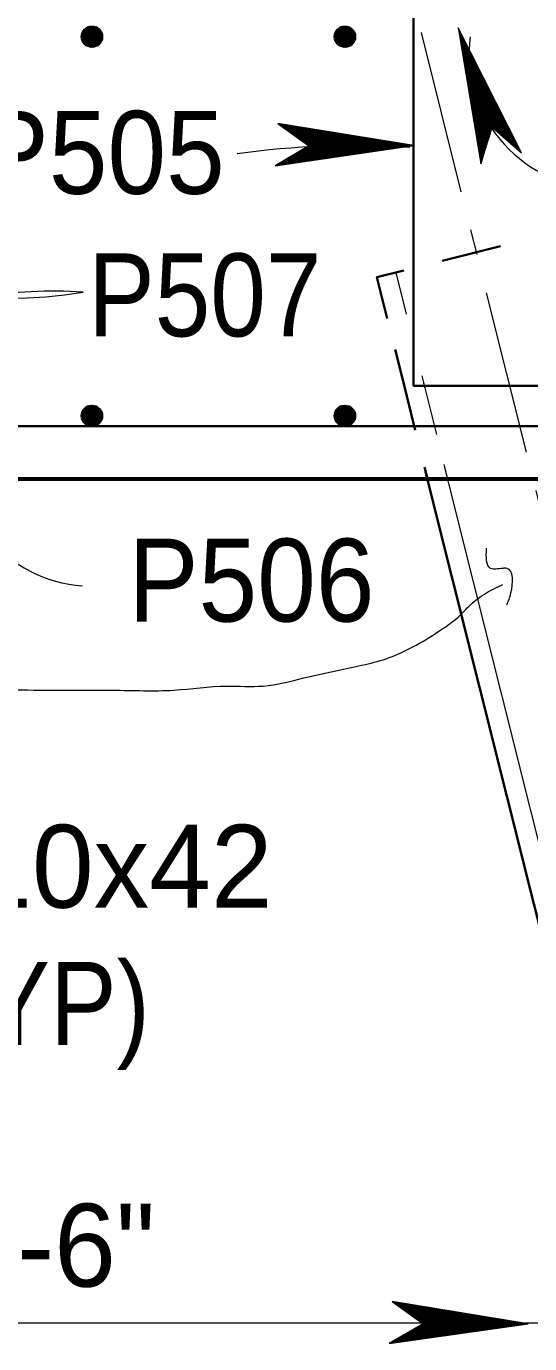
# Model space of a CAD drawing. Extents: x 144 to 252, y 360 to 425.
# Drawn here: x 193.57 to 195.56, y 408.41 to 413.62 of the extents above; entities that cross this region are included whole.
import ezdxf
from ezdxf.enums import TextEntityAlignment as Align

# ---------------------------------------------------------------- set-up
doc = ezdxf.new("R2010")
doc.units = 0
doc.header["$LTSCALE"] = 0.13
doc.linetypes.add('DOT_DASHED', pattern=[7.7, 5, -1.2, 0.3, -1.2])
for name, color, linetype, lineweight in [('1', 7, 'Continuous', 40), ('14', 7, 'Continuous', 13), ('16', 7, 'Continuous', 13), ('3', 7, 'Continuous', 13), ('4', 7, 'Continuous', 35), ('5', 7, 'Continuous', 35)]:
    doc.layers.add(name, color=color, linetype=linetype, lineweight=lineweight)

msp = doc.modelspace()

# ---------------------------------------------------------------- linework, layer by layer
at = {"layer": '1'}
for p, q in [((193.799, 413.6072), (193.7965, 413.5623)), ((193.8015, 413.6072), (193.799, 413.5623)), ((193.799, 413.6072), (193.859, 413.5972)), ((193.799, 413.6047), (193.859, 413.5947)), ((193.799, 413.6022), (193.859, 413.5897)), ((193.799, 413.5997), (193.859, 413.5872)), ((193.799, 413.5947), (193.8565, 413.5847)), ((193.8015, 413.6122), (193.859, 413.6022)), ((193.804, 413.6072), (193.8015, 413.5623)), ((193.8065, 413.6072), (193.804, 413.5623)), ((193.809, 413.6072), (193.8065, 413.5623)), ((193.814, 413.6072), (193.8115, 413.5623)), ((193.8165, 413.6072), (193.814, 413.5623)), ((193.819, 413.6072), (193.8165, 413.5623)), ((193.8215, 413.6072), (193.819, 413.5623)), ((193.824, 413.6072), (193.8215, 413.5623)), ((193.8265, 413.6072), (193.824, 413.5623)), ((193.829, 413.6072), (193.8265, 413.5623)), ((193.834, 413.6047), (193.829, 413.5598)), ((193.839, 413.6047), (193.834, 413.5598)), ((193.8415, 413.6047), (193.839, 413.5598)), ((193.8415, 413.6047), (193.839, 413.5598)), ((193.844, 413.6047), (193.8415, 413.5598)), ((193.8465, 413.6047), (193.844, 413.5598)), ((193.849, 413.6047), (193.8465, 413.5598)), ((193.8515, 413.6047), (193.849, 413.5598)), ((193.854, 413.6047), (193.8515, 413.5598)), ((193.8565, 413.6047), (193.854, 413.5598)), ((193.8615, 413.6047), (193.859, 413.5598)), ((194.799, 413.6072), (194.7965, 413.5623)), ((194.8015, 413.6072), (194.799, 413.5623)), ((194.799, 413.6072), (194.859, 413.5972)), ((194.799, 413.6047), (194.859, 413.5947)), ((194.799, 413.6022), (194.859, 413.5897)), ((194.799, 413.5997), (194.859, 413.5872)), ((194.799, 413.5947), (194.8565, 413.5847)), ((194.8015, 413.6122), (194.859, 413.6022)), ((194.804, 413.6072), (194.8015, 413.5623)), ((194.8065, 413.6072), (194.804, 413.5623)), ((194.809, 413.6072), (194.8065, 413.5623)), ((194.814, 413.6072), (194.8115, 413.5623)), ((194.8165, 413.6072), (194.814, 413.5623)), ((194.819, 413.6072), (194.8165, 413.5623)), ((194.8215, 413.6072), (194.819, 413.5623)), ((194.824, 413.6072), (194.8215, 413.5623)), ((194.8265, 413.6072), (194.824, 413.5623)), ((194.829, 413.6072), (194.8265, 413.5623)), ((194.834, 413.6047), (194.829, 413.5598)), ((194.839, 413.6047), (194.834, 413.5598)), ((194.8415, 413.6047), (194.839, 413.5598)), ((194.8415, 413.6047), (194.839, 413.5598)), ((194.844, 413.6047), (194.8415, 413.5598)), ((194.8465, 413.6047), (194.844, 413.5598)), ((194.849, 413.6047), (194.8465, 413.5598)), ((194.8515, 413.6047), (194.849, 413.5598)), ((194.854, 413.6047), (194.8515, 413.5598)), ((194.8565, 413.6047), (194.854, 413.5598)), ((194.8615, 413.6047), (194.859, 413.5598)), ((193.7915, 413.5648), (193.8515, 413.5548)), ((193.794, 413.5797), (193.854, 413.5673)), ((193.794, 413.5722), (193.854, 413.5623)), ((193.794, 413.5697), (193.8515, 413.5598)), ((193.794, 413.5673), (193.8515, 413.5573)), ((193.7965, 413.5922), (193.8565, 413.5822)), ((193.7965, 413.5897), (193.8565, 413.5772)), ((193.7965, 413.5872), (193.854, 413.5747)), ((193.7965, 413.5847), (193.854, 413.5722)), ((194.7915, 413.5648), (194.8515, 413.5548)), ((194.794, 413.5797), (194.854, 413.5673)), ((194.794, 413.5722), (194.854, 413.5623)), ((194.794, 413.5697), (194.8515, 413.5598)), ((194.794, 413.5673), (194.8515, 413.5573)), ((194.7965, 413.5922), (194.8565, 413.5822)), ((194.7965, 413.5897), (194.8565, 413.5772)), ((194.7965, 413.5872), (194.854, 413.5747)), ((194.7965, 413.5847), (194.854, 413.5722)), ((193.799, 412.1072), (193.7965, 412.0623)), ((193.7965, 412.0922), (193.8565, 412.0822)), ((193.7965, 412.0897), (193.8565, 412.0772)), ((193.7965, 412.0872), (193.854, 412.0747)), ((193.7965, 412.0847), (193.854, 412.0722)), ((193.8015, 412.1072), (193.799, 412.0623)), ((193.799, 412.1072), (193.859, 412.0972)), ((193.799, 412.1047), (193.859, 412.0947)), ((193.799, 412.1022), (193.859, 412.0897)), ((193.799, 412.0997), (193.859, 412.0872)), ((193.799, 412.0947), (193.8565, 412.0847)), ((193.8015, 412.1122), (193.859, 412.1022)), ((193.804, 412.1072), (193.8015, 412.0623)), ((193.8065, 412.1072), (193.804, 412.0623)), ((193.809, 412.1072), (193.8065, 412.0623)), ((193.814, 412.1072), (193.8115, 412.0623)), ((193.8165, 412.1072), (193.814, 412.0623)), ((193.819, 412.1072), (193.8165, 412.0623)), ((193.8215, 412.1072), (193.819, 412.0623)), ((193.824, 412.1072), (193.8215, 412.0623)), ((193.8265, 412.1072), (193.824, 412.0623)), ((193.829, 412.1072), (193.8265, 412.0623)), ((193.834, 412.1047), (193.829, 412.0598)), ((193.839, 412.1047), (193.834, 412.0598)), ((193.8415, 412.1047), (193.839, 412.0598)), ((193.8415, 412.1047), (193.839, 412.0598)), ((193.844, 412.1047), (193.8415, 412.0598)), ((193.8465, 412.1047), (193.844, 412.0598)), ((193.849, 412.1047), (193.8465, 412.0598)), ((193.8515, 412.1047), (193.849, 412.0598)), ((193.854, 412.1047), (193.8515, 412.0598)), ((193.8565, 412.1047), (193.854, 412.0598)), ((193.8615, 412.1047), (193.859, 412.0598)), ((194.799, 412.1072), (194.7965, 412.0623)), ((194.7965, 412.0922), (194.8565, 412.0822)), ((194.7965, 412.0897), (194.8565, 412.0772)), ((194.7965, 412.0872), (194.854, 412.0747)), ((194.7965, 412.0847), (194.854, 412.0722)), ((194.8015, 412.1072), (194.799, 412.0623)), ((194.799, 412.1072), (194.859, 412.0972)), ((194.799, 412.1047), (194.859, 412.0947)), ((194.799, 412.1022), (194.859, 412.0897)), ((194.799, 412.0997), (194.859, 412.0872)), ((194.799, 412.0947), (194.8565, 412.0847)), ((194.8015, 412.1122), (194.859, 412.1022)), ((194.804, 412.1072), (194.8015, 412.0623)), ((194.8065, 412.1072), (194.804, 412.0623)), ((194.809, 412.1072), (194.8065, 412.0623)), ((194.814, 412.1072), (194.8115, 412.0623)), ((194.8165, 412.1072), (194.814, 412.0623)), ((194.819, 412.1072), (194.8165, 412.0623)), ((194.8215, 412.1072), (194.819, 412.0623)), ((194.824, 412.1072), (194.8215, 412.0623)), ((194.8265, 412.1072), (194.824, 412.0623)), ((194.829, 412.1072), (194.8265, 412.0623)), ((194.834, 412.1047), (194.829, 412.0598)), ((194.839, 412.1047), (194.834, 412.0598)), ((194.8415, 412.1047), (194.839, 412.0598)), ((194.8415, 412.1047), (194.839, 412.0598)), ((194.844, 412.1047), (194.8415, 412.0598)), ((194.8465, 412.1047), (194.844, 412.0598)), ((194.849, 412.1047), (194.8465, 412.0598)), ((194.8515, 412.1047), (194.849, 412.0598)), ((194.854, 412.1047), (194.8515, 412.0598)), ((194.8565, 412.1047), (194.854, 412.0598)), ((194.8615, 412.1047), (194.859, 412.0598)), ((193.7915, 412.0648), (193.8515, 412.0548)), ((193.794, 412.0797), (193.854, 412.0673)), ((193.794, 412.0722), (193.854, 412.0623)), ((193.794, 412.0697), (193.8515, 412.0598)), ((193.794, 412.0673), (193.8515, 412.0573)), ((194.7915, 412.0648), (194.8515, 412.0548)), ((194.794, 412.0797), (194.854, 412.0673)), ((194.794, 412.0722), (194.854, 412.0623)), ((194.794, 412.0697), (194.8515, 412.0598)), ((194.794, 412.0673), (194.8515, 412.0573))]:
    msp.add_line(p, q, dxfattribs=at)
at = {"layer": '1', "lineweight": 60}
msp.add_lwpolyline([(190.824, 411.8347), (196.824, 411.8347), (196.824, 413.8347), (194.074, 413.8347), (194.074, 414.0847), (193.574, 414.0847), (193.574, 413.8347), (190.824, 413.8347)], close=True, dxfattribs=at)
at = {"layer": '1'}
for points in [[(193.7865, 413.5822), (193.864, 413.5922), (193.794, 413.6072), (193.864, 413.5747), (193.7915, 413.5623), (193.8515, 413.5522), (193.8515, 413.6147), (193.824, 413.5447), (193.8315, 413.6223), (193.8015, 413.5522), (193.8115, 413.6223), (193.8365, 413.5447), (193.789, 413.5972), (193.8615, 413.6022), (193.8115, 413.5472), (193.844, 413.6198), (193.794, 413.6072), (193.7915, 413.5623), (193.824, 413.5447), (193.8515, 413.5522), (193.864, 413.5747), (193.8615, 413.6022), (193.844, 413.6198), (193.824, 413.5872), (193.859, 413.5598), (193.8015, 413.5522), (193.824, 413.5872), (193.7915, 413.6022), (193.8215, 413.6223), (193.824, 413.5897), (193.849, 413.5522), (193.789, 413.5897), (193.829, 413.5997), (193.8515, 413.6147)], [(194.7865, 413.5822), (194.864, 413.5922), (194.794, 413.6072), (194.864, 413.5747), (194.7915, 413.5623), (194.8515, 413.5522), (194.8515, 413.6147), (194.824, 413.5447), (194.8315, 413.6223), (194.8015, 413.5522), (194.8115, 413.6223), (194.8365, 413.5447), (194.789, 413.5972), (194.8615, 413.6022), (194.8115, 413.5472), (194.844, 413.6198), (194.794, 413.6072), (194.7915, 413.5623), (194.824, 413.5447), (194.8515, 413.5522), (194.864, 413.5747), (194.8615, 413.6022), (194.844, 413.6198), (194.824, 413.5872), (194.859, 413.5598), (194.8015, 413.5522), (194.824, 413.5872), (194.7915, 413.6022), (194.8215, 413.6223), (194.824, 413.5897), (194.849, 413.5522), (194.789, 413.5897), (194.829, 413.5997), (194.8515, 413.6147)], [(193.7865, 412.0822), (193.864, 412.0922), (193.794, 412.1072), (193.864, 412.0747), (193.7915, 412.0623), (193.8515, 412.0522), (193.8515, 412.1147), (193.824, 412.0447), (193.8315, 412.1223), (193.8015, 412.0522), (193.8115, 412.1223), (193.8365, 412.0447), (193.789, 412.0972), (193.8615, 412.1022), (193.8115, 412.0472), (193.844, 412.1198), (193.794, 412.1072), (193.7915, 412.0623), (193.824, 412.0447), (193.8515, 412.0522), (193.864, 412.0747), (193.8615, 412.1022), (193.844, 412.1198), (193.824, 412.0872), (193.859, 412.0598), (193.8015, 412.0522), (193.824, 412.0872), (193.7915, 412.1022), (193.8215, 412.1223), (193.824, 412.0897), (193.849, 412.0522), (193.789, 412.0897), (193.829, 412.0997), (193.8515, 412.1147)], [(194.7865, 412.0822), (194.864, 412.0922), (194.794, 412.1072), (194.864, 412.0747), (194.7915, 412.0623), (194.8515, 412.0522), (194.8515, 412.1147), (194.824, 412.0447), (194.8315, 412.1223), (194.8015, 412.0522), (194.8115, 412.1223), (194.8365, 412.0447), (194.789, 412.0972), (194.8615, 412.1022), (194.8115, 412.0472), (194.844, 412.1198), (194.794, 412.1072), (194.7915, 412.0623), (194.824, 412.0447), (194.8515, 412.0522), (194.864, 412.0747), (194.8615, 412.1022), (194.844, 412.1198), (194.824, 412.0872), (194.859, 412.0598), (194.8015, 412.0522), (194.824, 412.0872), (194.7915, 412.1022), (194.8215, 412.1223), (194.824, 412.0897), (194.849, 412.0522), (194.789, 412.0897), (194.829, 412.0997), (194.8515, 412.1147)]]:
    msp.add_lwpolyline(points, dxfattribs=at)
for centre in [(193.8265, 413.5838), (194.8265, 413.5838), (193.8265, 412.0838), (194.8265, 412.0838)]:
    msp.add_circle(centre, 0.0396, dxfattribs=at)
at = {"layer": '1', "lineweight": 13}
msp.add_arc((193.4879, 414.4244), 1.8755, 208.5091, 279.3179, dxfattribs=at)
at = {"layer": '14', "lineweight": 35}
msp.add_lwpolyline([(195.0983, 415.7031), (195.0983, 412.2031), (196.0983, 412.2031)], dxfattribs=at)
at = {"layer": '14'}
for centre, radius, start, end in [((195.8515, 413.5165), 0.5336, 172.8262, 265.9116), ((194.8629, 409.8944), 3.2586, 86.1213, 98.1566), ((193.6769, 410.8499), 1.7275, 86.1945, 99.7709), ((193.827, 411.9433), 0.5336, 172.8262, 265.9116)]:
    msp.add_arc(centre, radius, start, end, dxfattribs=at)
at = {"layer": '16'}
for points in [[(195.4669, 411.336), (195.4829, 411.3842), (195.4669, 411.4805), (195.4508, 411.4805), (195.4027, 411.4805), (195.3866, 411.5608)], [(192.6731, 410.8222), (192.7534, 410.8704), (192.8818, 410.9347), (193.1227, 410.9667), (193.4278, 410.9988), (193.6204, 410.9988), (193.9094, 410.9988), (194.1502, 410.9988), (194.359, 411.0149), (194.5035, 411.0149), (194.6641, 411.047), (194.8086, 411.0792), (195.0012, 411.1273), (195.21, 411.2397), (195.2742, 411.2878), (195.3224, 411.336), (195.3866, 411.3842), (195.4508, 411.4163)]]:
    msp.add_spline(points, degree=3, dxfattribs=at)
at = {"layer": '3'}
for p, q in [((195.2741, 413.6187), (195.3636, 413.0812)), ((195.4086, 413.2257), (195.2741, 413.6187)), ((195.5252, 413.1247), (195.2741, 413.6187)), ((195.2781, 413.6048), (195.3648, 413.0848)), ((195.52, 413.1291), (195.2781, 413.6048)), ((195.2817, 413.5946), (195.366, 413.0888)), ((195.517, 413.1318), (195.2817, 413.5946)), ((195.2862, 413.5809), (195.3675, 413.0938)), ((195.513, 413.1353), (195.2862, 413.5809)), ((195.2904, 413.5688), (195.3688, 413.0982)), ((195.5094, 413.1383), (195.2904, 413.5688)), ((195.5094, 413.1383), (195.2904, 413.5688)), ((195.2941, 413.5582), (195.37, 413.1022)), ((195.5061, 413.1412), (195.2941, 413.5582)), ((195.2987, 413.5445), (195.3717, 413.1072)), ((195.5021, 413.1446), (195.2987, 413.5445)), ((195.3029, 413.5324), (195.3732, 413.1117)), ((195.4985, 413.1477), (195.3029, 413.5324)), ((195.3074, 413.5194), (195.3745, 413.1165)), ((195.4947, 413.1512), (195.3074, 413.5194)), ((195.3118, 413.5063), (195.3761, 413.1212)), ((195.4907, 413.1544), (195.3118, 413.5063)), ((195.3161, 413.4937), (195.3775, 413.1258)), ((195.487, 413.1577), (195.3161, 413.4937)), ((195.3206, 413.4806), (195.379, 413.1307)), ((195.4831, 413.161), (195.3206, 413.4806)), ((195.3247, 413.4687), (195.3803, 413.135)), ((195.4797, 413.164), (195.3247, 413.4687)), ((195.3283, 413.458), (195.3816, 413.1392)), ((195.4763, 413.1668), (195.3283, 413.458)), ((195.3335, 413.4431), (195.3833, 413.1447)), ((195.4722, 413.1707), (195.3335, 413.4431)), ((195.3379, 413.43), (195.3847, 413.1494)), ((195.4681, 413.174), (195.3379, 413.43)), ((195.3432, 413.4128), (195.3864, 413.1544)), ((195.4619, 413.1794), (195.3432, 413.4128)), ((195.4647, 413.1771), (195.3453, 413.4118)), ((195.3477, 413.3997), (195.3877, 413.1593)), ((195.458, 413.1828), (195.3477, 413.3997)), ((195.352, 413.3872), (195.3892, 413.1639)), ((195.4542, 413.186), (195.352, 413.3872)), ((195.3554, 413.3787), (195.3906, 413.1683)), ((195.453, 413.1872), (195.3554, 413.3787)), ((195.3593, 413.3674), (195.3918, 413.1726)), ((195.4495, 413.1902), (195.3593, 413.3674)), ((195.3637, 413.3542), (195.3935, 413.1774)), ((195.4456, 413.1936), (195.3637, 413.3542)), ((195.3688, 413.3395), (195.3949, 413.1828)), ((195.4413, 413.1972), (195.3688, 413.3395)), ((195.373, 413.3277), (195.3964, 413.1872)), ((195.4377, 413.2003), (195.373, 413.3277)), ((195.3773, 413.3151), (195.3978, 413.1918)), ((195.434, 413.2036), (195.3773, 413.3151)), ((195.3811, 413.3037), (195.3992, 413.1962)), ((195.4306, 413.2065), (195.3811, 413.3037)), ((195.3858, 413.29), (195.4006, 413.2011)), ((195.4266, 413.2099), (195.3858, 413.29)), ((195.0994, 413.1533), (194.5614, 413.2403)), ((194.5614, 413.2403), (194.6842, 413.1518)), ((195.085, 413.1539), (194.5647, 413.2381)), ((195.0742, 413.1539), (194.5679, 413.2357)), ((195.0597, 413.1539), (194.5722, 413.2326)), ((195.047, 413.1538), (194.5759, 413.2299)), ((195.3903, 413.2769), (195.4021, 413.206)), ((195.4227, 413.2133), (195.3903, 413.2769)), ((195.3944, 413.2649), (195.4036, 413.2103)), ((195.4192, 413.2165), (195.3944, 413.2649)), ((195.3988, 413.2524), (195.405, 413.2149)), ((195.4024, 413.2416), (195.4062, 413.219)), ((195.4122, 413.2224), (195.4024, 413.2416)), ((195.4145, 413.2204), (195.403, 413.243)), ((195.4056, 413.232), (195.4073, 413.2226)), ((195.0357, 413.1538), (194.5793, 413.2276)), ((195.0212, 413.1538), (194.5835, 413.2244)), ((195.0085, 413.1537), (194.5872, 413.2217)), ((194.9947, 413.1536), (194.5914, 413.2188)), ((194.981, 413.1535), (194.5955, 413.2158)), ((194.9677, 413.1534), (194.5994, 413.2129)), ((194.9537, 413.1534), (194.6035, 413.21)), ((194.9412, 413.1534), (194.6072, 413.2073)), ((194.9297, 413.1533), (194.6107, 413.2049)), ((194.9141, 413.1533), (194.6153, 413.2015)), ((194.9002, 413.1532), (194.6194, 413.1985)), ((194.8822, 413.1536), (194.6237, 413.1955)), ((194.8683, 413.1536), (194.6278, 413.1925)), ((194.8552, 413.1535), (194.6317, 413.1897)), ((194.8461, 413.1529), (194.6355, 413.187)), ((194.8342, 413.1529), (194.6391, 413.1843)), ((194.8202, 413.1528), (194.6432, 413.1813)), ((194.8046, 413.1528), (194.6478, 413.1782)), ((195.3636, 413.0812), (195.4083, 413.2258)), ((195.4083, 413.2258), (195.5252, 413.1247)), ((194.551, 413.0733), (195.0994, 413.1533)), ((194.6842, 413.1518), (194.551, 413.0733)), ((194.557, 413.0768), (195.085, 413.1539)), ((194.5604, 413.0788), (195.0742, 413.1539)), ((194.5651, 413.0816), (195.0597, 413.1539)), ((194.5691, 413.084), (195.047, 413.1538)), ((194.5691, 413.084), (195.047, 413.1538)), ((194.5727, 413.0862), (195.0357, 413.1538)), ((194.5774, 413.0888), (195.0212, 413.1538)), ((194.5814, 413.0913), (195.0085, 413.1537)), ((194.5858, 413.0938), (194.9947, 413.1536)), ((194.5902, 413.0964), (194.981, 413.1535)), ((194.5945, 413.099), (194.9677, 413.1534)), ((194.5989, 413.1016), (194.9537, 413.1534)), ((194.6029, 413.1039), (194.9412, 413.1534)), ((194.6067, 413.1062), (194.9297, 413.1533)), ((194.6117, 413.109), (194.9141, 413.1533)), ((194.6162, 413.1117), (194.9002, 413.1532)), ((194.6201, 413.1139), (194.8808, 413.152)), ((194.6232, 413.1158), (194.8822, 413.1536)), ((194.6277, 413.1185), (194.8683, 413.1536)), ((194.6319, 413.121), (194.8552, 413.1535)), ((194.6334, 413.1218), (194.8461, 413.1529)), ((194.6373, 413.1242), (194.8342, 413.1529)), ((194.6417, 413.1267), (194.8202, 413.1528)), ((194.6467, 413.1297), (194.8046, 413.1528)), ((194.6507, 413.1321), (194.792, 413.1527)), ((194.792, 413.1527), (194.6515, 413.1754)), ((194.655, 413.1347), (194.7788, 413.1527)), ((194.7788, 413.1527), (194.6554, 413.1727)), ((194.6588, 413.1369), (194.7668, 413.1526)), ((194.7668, 413.1526), (194.6591, 413.1699)), ((194.7523, 413.1526), (194.6633, 413.167)), ((194.6635, 413.1396), (194.7523, 413.1526)), ((194.7384, 413.1526), (194.6674, 413.164)), ((194.6679, 413.1421), (194.7384, 413.1526)), ((194.7258, 413.1524), (194.6711, 413.1612)), ((194.672, 413.1445), (194.7258, 413.1524)), ((194.7125, 413.1525), (194.675, 413.1585)), ((194.6772, 413.1476), (194.7022, 413.1513)), ((194.7011, 413.1524), (194.6785, 413.156)), ((194.6798, 413.1492), (194.7011, 413.1524)), ((194.691, 413.1523), (194.6815, 413.1538)), ((194.684, 413.1517), (195.0994, 413.1533)), ((195.5508, 408.4911), (195.0132, 408.5803)), ((195.0132, 408.5803), (195.1357, 408.4912)), ((195.5364, 408.4917), (195.0164, 408.578)), ((195.5256, 408.4917), (195.0197, 408.5757)), ((195.5112, 408.4917), (195.0239, 408.5725)), ((195.4984, 408.4917), (195.0277, 408.5698)), ((195.4871, 408.4917), (195.031, 408.5674)), ((195.4727, 408.4917), (195.0352, 408.5642)), ((195.4599, 408.4917), (195.039, 408.5615)), ((195.4462, 408.4917), (195.0431, 408.5586)), ((195.4323, 408.4917), (195.0472, 408.5556)), ((195.4191, 408.4917), (195.0511, 408.5528)), ((195.4052, 408.4917), (195.0552, 408.5497)), ((195.3926, 408.4917), (195.0589, 408.5471)), ((195.3812, 408.4917), (195.0623, 408.5446)), ((195.3655, 408.4917), (195.0669, 408.5412)), ((195.3517, 408.4917), (195.071, 408.5383)), ((196.8157, 408.4941), (190.833, 408.4941)), ((195.1357, 408.4912), (195.0021, 408.4133)), ((195.0021, 408.4133), (195.5508, 408.4911)), ((195.0081, 408.4168), (195.5364, 408.4917)), ((195.0116, 408.4188), (195.5256, 408.4917)), ((195.0162, 408.4215), (195.5112, 408.4917)), ((195.0203, 408.4239), (195.4984, 408.4917)), ((195.0203, 408.4239), (195.4984, 408.4917)), ((195.0239, 408.4261), (195.4871, 408.4917)), ((195.0285, 408.4287), (195.4727, 408.4917)), ((195.0326, 408.4312), (195.4599, 408.4917)), ((195.037, 408.4337), (195.4462, 408.4917)), ((195.0414, 408.4362), (195.4323, 408.4917)), ((195.0457, 408.4387), (195.4191, 408.4917)), ((195.0502, 408.4414), (195.4052, 408.4917)), ((195.0542, 408.4437), (195.3926, 408.4917)), ((195.0579, 408.4459), (195.3812, 408.4917)), ((195.0629, 408.4487), (195.3655, 408.4917)), ((195.0673, 408.4514), (195.3517, 408.4917)), ((195.0713, 408.4537), (195.3321, 408.4907)), ((195.0745, 408.4556), (195.3337, 408.4923)), ((195.3337, 408.4923), (195.0752, 408.5352)), ((195.0789, 408.4582), (195.3197, 408.4923)), ((195.3197, 408.4923), (195.0794, 408.5322)), ((195.3066, 408.4923), (195.0832, 408.5293)), ((195.0832, 408.4607), (195.3066, 408.4923)), ((195.0847, 408.4615), (195.2975, 408.4917)), ((195.2975, 408.4917), (195.087, 408.5266)), ((195.0886, 408.4638), (195.2855, 408.4917)), ((195.2855, 408.4917), (195.0906, 408.524)), ((195.093, 408.4664), (195.2717, 408.4917)), ((195.2717, 408.4917), (195.0947, 408.521)), ((195.098, 408.4692), (195.256, 408.4917)), ((195.256, 408.4917), (195.0993, 408.5177)), ((195.1021, 408.4717), (195.2434, 408.4917)), ((195.2434, 408.4917), (195.103, 408.515)), ((195.1063, 408.4742), (195.2302, 408.4917)), ((195.2302, 408.4917), (195.1069, 408.5122)), ((195.1102, 408.4764), (195.2182, 408.4917)), ((195.2182, 408.4917), (195.1105, 408.5095)), ((195.2037, 408.4917), (195.1147, 408.5065)), ((195.1148, 408.4791), (195.2037, 408.4917)), ((195.1898, 408.4917), (195.1189, 408.5035)), ((195.1192, 408.4817), (195.1898, 408.4917)), ((195.1772, 408.4917), (195.1226, 408.5007)), ((195.1233, 408.484), (195.1772, 408.4917)), ((195.1639, 408.4917), (195.1265, 408.4979)), ((195.1286, 408.4871), (195.1537, 408.4907)), ((195.1525, 408.4917), (195.1299, 408.4955)), ((195.1312, 408.4887), (195.1525, 408.4917)), ((195.1423, 408.4917), (195.1329, 408.4932)), ((195.1354, 408.4911), (195.5508, 408.4911))]:
    msp.add_line(p, q, dxfattribs=at)
at = {"layer": '4'}
msp.add_line((191.074, 412.0431), (196.574, 412.0431), dxfattribs=at)
at = {"layer": '5', "linetype": 'DOT_DASHED', "lineweight": 13}
msp.add_line((195.1278, 413.6012), (196.238, 409.1598), dxfattribs=at)
at = {"layer": '5'}
for p, q in [((195.4415, 412.7548), (195.2113, 412.6972)), ((195.0248, 412.3467), (195.0655, 412.1839)), ((195.055, 412.226), (195.1048, 412.0269)), ((195.1412, 411.8815), (195.1538, 411.8312)), ((195.1458, 411.8627), (195.6808, 409.7222))]:
    msp.add_line(p, q, dxfattribs=at)
at = {"layer": '5', "lineweight": 13}
for p, q in [((195.0277, 412.6513), (195.0688, 412.4867)), ((195.1301, 412.2416), (195.188, 412.0099)), ((195.1372, 412.2128), (195.1417, 412.195)), ((195.2177, 411.8914), (195.2318, 411.8347)), ((195.2205, 411.8798), (195.7552, 409.7408))]:
    msp.add_line(p, q, dxfattribs=at)
at = {"layer": '5'}
msp.add_lwpolyline([(195.0601, 412.6594), (194.9533, 412.6327), (194.9942, 412.469)], dxfattribs=at)

# ---------------------------------------------------------------- texts
at = {"layer": '14'}
for s, width, p in [('P505', 0.95, (193.8647, 412.9623)), ('P507', 0.9, (194.2726, 412.3984)), ('P506', 0.95, (194.4567, 411.27))]:
    msp.add_text(s, height=0.3281, dxfattribs=dict(at, width=width)).set_placement(p, align=Align.CENTER)
at = {"layer": '16'}
for s, p in [('HP 10x42', (193.5775, 410.138)), ('3\'-6"', (193.6401, 408.6388))]:
    msp.add_text(s, height=0.3281, dxfattribs=at).set_placement(p, align=Align.CENTER)
at = {"layer": '16', "width": 0.9}
msp.add_text('(TYP)', height=0.3281, dxfattribs=at).set_placement((193.5401, 409.5953), align=Align.CENTER)

doc.saveas('drawing.dxf')
